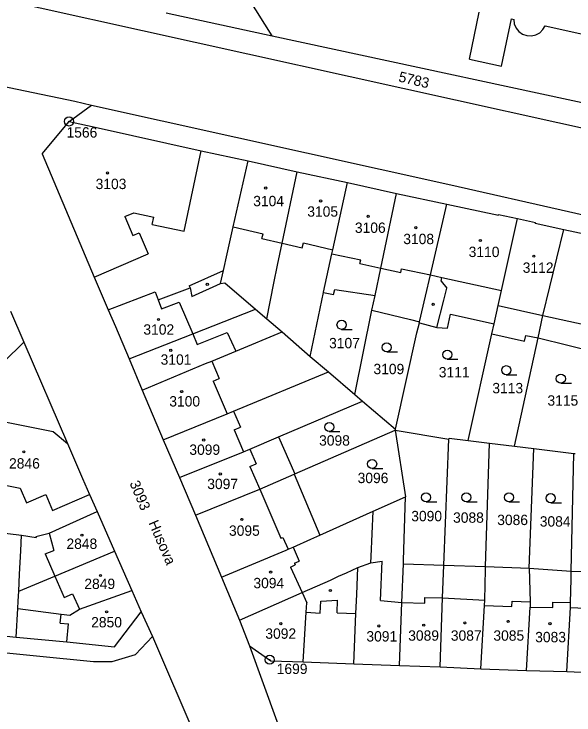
# Model space of a CAD drawing. Extents: x -735092 to -733385, y -1122435 to -1118992.
# Drawn here: x -734755 to -734663.1, y -1120137.2 to -1120022.1 of the extents above; entities that cross this region are included whole.
import ezdxf

# ---------------------------------------------------------------- set-up
doc = ezdxf.new("R2010")
doc.units = 0
for name, color, linetype in [('Vrstva 1', 7, 'Continuous'), ('Vrstva 15', 7, 'Continuous'), ('Vrstva 17', 7, 'Continuous'), ('Vrstva 18', 7, 'Continuous'), ('Vrstva 19', 7, 'Continuous'), ('Vrstva 25', 7, 'Continuous'), ('Vrstva 4', 7, 'Continuous')]:
    doc.layers.add(name, color=color, linetype=linetype)

msp = doc.modelspace()

# ---------------------------------------------------------------- linework, layer by layer
at = {"layer": 'Vrstva 1'}
for points in [[(-734712.66, -1120025.63), (-734719.23, -1120015.12)], [(-734759.44, -1120019.08), (-734622.96, -1120049.35)], [(-734730.04, -1120021.87), (-734712.66, -1120025.63)], [(-734680.22, -1120029.49), (-734678.62, -1120021.76)], [(-734674.99, -1120030.64), (-734673.34, -1120022.87)], [(-734673.34, -1120022.87), (-734672.95, -1120022.95)], [(-734672.95, -1120022.95), (-734672.86, -1120023.68)], [(-734672.86, -1120023.68), (-734672.57, -1120024.36)], [(-734672.57, -1120024.36), (-734672.1, -1120024.94)], [(-734668.17, -1120024.62), (-734667.8, -1120023.98)], [(-734667.8, -1120023.98), (-734657.17, -1120026.38)], [(-734712.66, -1120025.63), (-734649.52, -1120039.21)], [(-734672.1, -1120024.94), (-734671.5, -1120025.36)], [(-734671.5, -1120025.36), (-734670.8, -1120025.6)], [(-734670.8, -1120025.6), (-734670.06, -1120025.64)], [(-734670.06, -1120025.64), (-734669.34, -1120025.48)], [(-734669.34, -1120025.48), (-734668.69, -1120025.13)], [(-734668.69, -1120025.13), (-734668.17, -1120024.62)], [(-734680.22, -1120029.49), (-734674.99, -1120030.64)], [(-734773.55, -1120030.48), (-734745.06, -1120036.39)], [(-734746.01, -1120039.7), (-734742.29, -1120037.01)], [(-734745.06, -1120036.39), (-734742.29, -1120037.01)], [(-734742.29, -1120037.01), (-734683.27, -1120050.12)], [(-734750.43, -1120045), (-734746.01, -1120039.7)], [(-734746.01, -1120039.7), (-734741.21, -1120040.76)], [(-734741.21, -1120040.76), (-734724.28, -1120044.52)], [(-734750.43, -1120045), (-734741.89, -1120065.28)], [(-734724.28, -1120044.52), (-734716.58, -1120046.19)], [(-734719.02, -1120057.03), (-734716.58, -1120046.19)], [(-734716.58, -1120046.19), (-734708.51, -1120047.95)], [(-734711.01, -1120059.7), (-734708.51, -1120047.95)], [(-734708.51, -1120047.95), (-734700.29, -1120049.73)], [(-734702.69, -1120060.78), (-734700.29, -1120049.73)], [(-734700.29, -1120049.73), (-734692.22, -1120051.53)], [(-734683.27, -1120050.12), (-734625.28, -1120063.27)], [(-734694.8, -1120063.78), (-734692.22, -1120051.53)], [(-734692.22, -1120051.53), (-734683.93, -1120053.29)], [(-734686.63, -1120064.91), (-734683.93, -1120053.29)], [(-734683.93, -1120053.29), (-734675.47, -1120055.11)], [(-734675.47, -1120055.11), (-734675.44, -1120054.97)], [(-734675.44, -1120054.97), (-734672.36, -1120055.63)], [(-734674.98, -1120067.47), (-734672.36, -1120055.63)], [(-734672.36, -1120055.63), (-734669.4, -1120056.27)], [(-734669.43, -1120056.41), (-734669.4, -1120056.27)], [(-734669.43, -1120056.41), (-734664.74, -1120057.42)], [(-734720.02, -1120061.44), (-734719.02, -1120057.03)], [(-734668.15, -1120071.54), (-734664.74, -1120057.42)], [(-734664.74, -1120057.42), (-734658.29, -1120058.81)], [(-734711.75, -1120063.31), (-734711.01, -1120059.7)], [(-734704.2, -1120067.71), (-734702.83, -1120061.43)], [(-734702.83, -1120061.43), (-734702.69, -1120060.78)], [(-734720.64, -1120064.2), (-734720.02, -1120061.44)], [(-734712.35, -1120066.27), (-734711.75, -1120063.31)], [(-734721.12, -1120066.31), (-734720.64, -1120064.2)], [(-734695.74, -1120068.26), (-734694.8, -1120063.78)], [(-734741.89, -1120065.28), (-734739.58, -1120070.62)], [(-734687.44, -1120068.41), (-734686.63, -1120064.91)], [(-734731.38, -1120068.98), (-734726.12, -1120067.04)], [(-734726.12, -1120067.04), (-734725.84, -1120068.43)], [(-734725.84, -1120068.43), (-734721.12, -1120066.31)], [(-734721.12, -1120066.31), (-734720.44, -1120066.19)], [(-734720.44, -1120066.19), (-734715.39, -1120070.51)], [(-734713.54, -1120072.09), (-734712.35, -1120066.27)], [(-734739.58, -1120070.62), (-734731.88, -1120067.67)], [(-734731.88, -1120067.67), (-734731.38, -1120068.98)], [(-734706.4, -1120078.29), (-734704.22, -1120067.79)], [(-734704.22, -1120067.79), (-734704.2, -1120067.71)], [(-734704.22, -1120067.79), (-734702.54, -1120068.14)], [(-734702.54, -1120068.14), (-734702.37, -1120067.32)], [(-734702.37, -1120067.32), (-734695.74, -1120068.26)], [(-734696.24, -1120070.7), (-734695.74, -1120068.26)], [(-734675.52, -1120069.92), (-734674.98, -1120067.47)], [(-734688.41, -1120072.59), (-734687.44, -1120068.41)], [(-734739.58, -1120070.62), (-734738.38, -1120073.38)], [(-734725.68, -1120074.58), (-734715.39, -1120070.51)], [(-734715.39, -1120070.51), (-734713.54, -1120072.09)], [(-734676.18, -1120072.92), (-734675.52, -1120069.92)], [(-734755.61, -1120070.88), (-734753.42, -1120075.94)], [(-734699.07, -1120084.53), (-734696.24, -1120070.7)], [(-734696.24, -1120070.7), (-734689.9, -1120072.25)], [(-734683.86, -1120073.64), (-734683.35, -1120071.33)], [(-734683.35, -1120071.33), (-734676.18, -1120072.92)], [(-734668.96, -1120075.25), (-734668.15, -1120071.54)], [(-734713.54, -1120072.09), (-734710.98, -1120074.27)], [(-734689.9, -1120072.25), (-734688.41, -1120072.59)], [(-734688.87, -1120074.42), (-734688.46, -1120072.79)], [(-734688.46, -1120072.79), (-734688.41, -1120072.59)], [(-734688.46, -1120072.79), (-734685.58, -1120073.52)], [(-734676.55, -1120074.57), (-734676.18, -1120072.92)], [(-734738.38, -1120073.38), (-734736.13, -1120078.7)], [(-734685.58, -1120073.52), (-734683.86, -1120073.64)], [(-734736.13, -1120078.7), (-734725.68, -1120074.58)], [(-734718.6, -1120077.41), (-734710.98, -1120074.27)], [(-734710.98, -1120074.27), (-734706.4, -1120078.29)], [(-734692.37, -1120090.23), (-734688.87, -1120074.42)], [(-734680.42, -1120092.08), (-734676.55, -1120074.57)], [(-734676.55, -1120074.57), (-734671.19, -1120075.76)], [(-734671.19, -1120075.76), (-734670.99, -1120074.84)], [(-734670.99, -1120074.84), (-734668.96, -1120075.25)], [(-734756.74, -1120079.17), (-734753.42, -1120075.94)], [(-734753.42, -1120075.94), (-734746.27, -1120092.6)], [(-734672.81, -1120093.01), (-734668.96, -1120075.25)], [(-734668.96, -1120075.25), (-734659.21, -1120077.63)], [(-734722.56, -1120079.04), (-734718.6, -1120077.41)], [(-734706.4, -1120078.29), (-734703.41, -1120080.84)], [(-734736.13, -1120078.7), (-734734, -1120083.8)], [(-734734, -1120083.8), (-734723.58, -1120079.46)], [(-734723.58, -1120079.46), (-734722.56, -1120079.04)], [(-734718.98, -1120087.3), (-734703.41, -1120080.84)], [(-734703.41, -1120080.84), (-734699.07, -1120084.53)], [(-734734, -1120083.8), (-734730.53, -1120091.97)], [(-734699.07, -1120084.53), (-734697.79, -1120085.62)], [(-734711.61, -1120091.5), (-734697.79, -1120085.62)], [(-734697.79, -1120085.62), (-734692.37, -1120090.23)], [(-734730.53, -1120091.97), (-734720.01, -1120087.73)], [(-734720.01, -1120087.73), (-734718.98, -1120087.3)], [(-734759.88, -1120088.36), (-734748.62, -1120090.64)], [(-734748.62, -1120090.64), (-734746.27, -1120092.6)], [(-734708.91, -1120097.56), (-734692.41, -1120090.4)], [(-734692.41, -1120090.4), (-734692.37, -1120090.23)], [(-734692.41, -1120090.4), (-734690.71, -1120101.34)], [(-734692.41, -1120090.4), (-734683.6, -1120091.87)], [(-734730.53, -1120091.97), (-734727.88, -1120098.19)], [(-734716.31, -1120093.5), (-734711.61, -1120091.5)], [(-734711.61, -1120091.5), (-734708.91, -1120097.56)], [(-734684.42, -1120112.56), (-734683.6, -1120091.87)], [(-734683.6, -1120091.87), (-734683.59, -1120091.7)], [(-734683.59, -1120091.7), (-734680.42, -1120092.08)], [(-734680.42, -1120092.08), (-734676.96, -1120092.51)], [(-734677.59, -1120112.79), (-734676.96, -1120092.51)], [(-734676.96, -1120092.51), (-734672.81, -1120093.01)], [(-734746.27, -1120092.6), (-734743.81, -1120098.34)], [(-734717.33, -1120093.93), (-734716.31, -1120093.5)], [(-734672.81, -1120093.01), (-734669.67, -1120093.4)], [(-734670.4, -1120113.05), (-734669.67, -1120093.4)], [(-734669.67, -1120093.4), (-734663.11, -1120094.23)], [(-734727.88, -1120098.19), (-734717.33, -1120093.93)], [(-734663.52, -1120113.54), (-734663.11, -1120094.23)], [(-734663.11, -1120094.23), (-734662.86, -1120094.24)], [(-734727.88, -1120098.19), (-734725.22, -1120104.37)], [(-734714.69, -1120100.06), (-734709.02, -1120097.6)], [(-734709.02, -1120097.6), (-734708.91, -1120097.56)], [(-734709.02, -1120097.6), (-734704.79, -1120107.63)], [(-734743.81, -1120098.34), (-734742.65, -1120100.94)], [(-734725.22, -1120104.37), (-734714.69, -1120100.06)], [(-734742.65, -1120100.94), (-734741.41, -1120103.73)], [(-734696.03, -1120103.72), (-734690.71, -1120101.34)], [(-734691.04, -1120111.73), (-734690.71, -1120101.34)], [(-734749.29, -1120107.32), (-734741.41, -1120103.73)], [(-734741.41, -1120103.73), (-734738.55, -1120110.28)], [(-734704.79, -1120107.63), (-734696.03, -1120103.72)], [(-734696.4, -1120111.12), (-734696.03, -1120103.72)], [(-734978.31, -1120104.89), (-734741.96, -1120128.37)], [(-734725.22, -1120104.37), (-734720.97, -1120114.53)], [(-734762.86, -1120106.55), (-734753.79, -1120107.64)], [(-734751.46, -1120107.88), (-734749.29, -1120107.32)], [(-734753.92, -1120110.19), (-734753.79, -1120107.64)], [(-734753.79, -1120107.64), (-734751.4, -1120108.03)], [(-734751.46, -1120107.88), (-734751.4, -1120108.03)], [(-734709.2, -1120109.6), (-734706.3, -1120108.3)], [(-734706.3, -1120108.3), (-734704.79, -1120107.63)], [(-734710.03, -1120109.96), (-734709.2, -1120109.6)], [(-734754.12, -1120114.04), (-734753.92, -1120110.19)], [(-734748.32, -1120114.37), (-734738.55, -1120110.28)], [(-734738.55, -1120110.28), (-734735.7, -1120116.71)], [(-734720.97, -1120114.53), (-734710.35, -1120110.11)], [(-734710.35, -1120110.11), (-734710.03, -1120109.96)], [(-734696.45, -1120112.2), (-734696.4, -1120111.12)], [(-734691.06, -1120112.35), (-734691.04, -1120111.73)], [(-734700.44, -1120113.83), (-734698.55, -1120112.94)], [(-734698.74, -1120117.36), (-734698.55, -1120112.94)], [(-734698.55, -1120112.94), (-734696.45, -1120112.2)], [(-734691.32, -1120118.72), (-734691.06, -1120112.35)], [(-734691.06, -1120112.35), (-734684.42, -1120112.56)], [(-734684.64, -1120117.95), (-734684.42, -1120112.56)], [(-734684.42, -1120112.56), (-734677.59, -1120112.79)], [(-734677.6, -1120113.26), (-734677.59, -1120112.79)], [(-734677.59, -1120112.79), (-734670.4, -1120113.05)], [(-734670.4, -1120113.05), (-734663.52, -1120113.54)], [(-734670.4, -1120113.05), (-734670.28, -1120118.59)], [(-734754.25, -1120116.86), (-734754.12, -1120114.04)], [(-734754.25, -1120116.86), (-734748.32, -1120114.37)], [(-734703.08, -1120115.02), (-734701.75, -1120114.37)], [(-734701.75, -1120114.37), (-734700.44, -1120113.83)], [(-734677.72, -1120118.31), (-734677.6, -1120113.26)], [(-734663.55, -1120114.85), (-734663.52, -1120113.54)], [(-734663.52, -1120113.54), (-734658.19, -1120113.59)], [(-734720.97, -1120114.53), (-734717.99, -1120121.62)], [(-734707.73, -1120117.04), (-734703.08, -1120115.02)], [(-734663.62, -1120118.67), (-734663.55, -1120114.85)], [(-734754.35, -1120118.5), (-734754.25, -1120116.86)], [(-734744.27, -1120119.8), (-734735.7, -1120116.71)], [(-734735.7, -1120116.71), (-734734.16, -1120120.2)], [(-734717.99, -1120121.62), (-734707.73, -1120117.04)], [(-734698.88, -1120120.5), (-734698.74, -1120117.36)], [(-734754.43, -1120119.69), (-734754.35, -1120118.5)], [(-734691.73, -1120129.02), (-734691.32, -1120118.72)], [(-734685.05, -1120129.27), (-734684.64, -1120117.95)], [(-734677.74, -1120119.17), (-734677.72, -1120118.31)], [(-734670.28, -1120118.59), (-734670.26, -1120119.45)], [(-734663.63, -1120119.54), (-734663.62, -1120118.67)], [(-734754.69, -1120124.4), (-734754.43, -1120119.69)], [(-734754.43, -1120119.69), (-734747.32, -1120120.59)], [(-734745.89, -1120120.77), (-734744.27, -1120119.8)], [(-734678.37, -1120129.56), (-734677.74, -1120119.17)], [(-734670.88, -1120129.86), (-734670.26, -1120119.45)], [(-734664.23, -1120130.05), (-734663.63, -1120119.54)], [(-734747.32, -1120120.59), (-734745.89, -1120120.77)], [(-734738.56, -1120125.97), (-734734.16, -1120120.2)], [(-734734.16, -1120120.2), (-734732.31, -1120124.29)], [(-734699.23, -1120128.75), (-734698.88, -1120120.5)], [(-734717.99, -1120121.62), (-734716.35, -1120125.79)], [(-734759.45, -1120123.9), (-734754.69, -1120124.4)], [(-734754.69, -1120124.4), (-734746.39, -1120125.14)], [(-734735.07, -1120127.22), (-734732.31, -1120124.29)], [(-734732.31, -1120124.29), (-734725.18, -1120140.86)], [(-734746.39, -1120125.14), (-734738.56, -1120125.97)], [(-734716.35, -1120125.79), (-734713.42, -1120127.87)], [(-734716.35, -1120125.79), (-734709.6, -1120144.34)], [(-734738.9, -1120128.4), (-734735.07, -1120127.22)], [(-734713.42, -1120127.87), (-734712.88, -1120128.26)], [(-734741.96, -1120128.37), (-734738.9, -1120128.4)], [(-734712.88, -1120128.26), (-734707.54, -1120128.46)], [(-734707.54, -1120128.46), (-734699.23, -1120128.75)], [(-734699.23, -1120128.75), (-734691.73, -1120129.02)], [(-734691.73, -1120129.02), (-734685.05, -1120129.27)], [(-734685.05, -1120129.27), (-734678.37, -1120129.56)], [(-734678.37, -1120129.56), (-734670.88, -1120129.86)], [(-734670.88, -1120129.86), (-734664.23, -1120130.05)], [(-734664.23, -1120130.05), (-734653.23, -1120130.5)]]:
    msp.add_lwpolyline(points, dxfattribs=at)
at = {"layer": 'Vrstva 25'}
for points in [[(-734701.24, -1120073.84), (-734699.49, -1120073.84)], [(-734693.82, -1120077.55), (-734692.07, -1120077.55)], [(-734683.88, -1120078.74), (-734682.13, -1120078.74)], [(-734674.18, -1120081.3), (-734672.43, -1120081.3)], [(-734665.22, -1120082.69), (-734663.47, -1120082.69)], [(-734703.26, -1120090.64), (-734701.51, -1120090.64)], [(-734696.22, -1120096.7), (-734694.47, -1120096.7)], [(-734687.36, -1120102.18), (-734685.61, -1120102.18)], [(-734680.74, -1120102.18), (-734678.99, -1120102.18)], [(-734673.75, -1120102.18), (-734672, -1120102.18)], [(-734666.88, -1120102.31), (-734665.13, -1120102.31)]]:
    msp.add_lwpolyline(points, dxfattribs=at)
for centre, radius in [((-734746.01, -1120039.7), 0.75), ((-734746.01, -1120039.7), 0.032), ((-734739.7, -1120048.16), 0.175), ((-734713.7, -1120050.64), 0.175), ((-734704.68, -1120052.76), 0.175), ((-734696.86, -1120055.28), 0.175), ((-734689.04, -1120057.14), 0.175), ((-734678.44, -1120059.26), 0.175), ((-734669.65, -1120061.81), 0.175), ((-734723.29, -1120066.44), 0.175), ((-734686.2, -1120069.74), 0.175), ((-734731.32, -1120072.23), 0.175), ((-734701.24, -1120073.09), 0.75), ((-734693.82, -1120076.8), 0.75), ((-734729.3, -1120077.29), 0.175), ((-734683.88, -1120077.99), 0.75), ((-734674.18, -1120080.55), 0.75), ((-734665.22, -1120081.94), 0.75), ((-734727.5, -1120084.06), 0.175), ((-734703.26, -1120089.89), 0.75), ((-734723.89, -1120092.02), 0.175), ((-734753.42, -1120093.95), 0.175), ((-734696.22, -1120095.95), 0.75), ((-734721.16, -1120097.59), 0.174), ((-734687.36, -1120101.43), 0.75), ((-734680.74, -1120101.43), 0.75), ((-734673.75, -1120101.43), 0.75), ((-734666.88, -1120101.56), 0.75), ((-734717.62, -1120105.05), 0.175), ((-734743.89, -1120107.65), 0.175), ((-734740.85, -1120114.25), 0.175), ((-734712.89, -1120113.7), 0.175), ((-734703.08, -1120116.73), 0.175), ((-734739.83, -1120120.24), 0.175), ((-734711.22, -1120122.17), 0.175), ((-734695.11, -1120122.55), 0.175), ((-734687.74, -1120122.42), 0.175), ((-734680.99, -1120122.05), 0.175), ((-734673.87, -1120121.8), 0.175), ((-734667, -1120122.17), 0.175), ((-734713.05, -1120128.09), 0.75), ((-734713.05, -1120128.09), 0.032)]:
    msp.add_circle(centre, radius, dxfattribs=at)
at = {"layer": 'Vrstva 4'}
for points in [[(-734727.08, -1120057.7), (-734724.28, -1120044.52)], [(-734736.83, -1120055.33), (-734735.35, -1120054.73)], [(-734736.83, -1120055.33), (-734735.52, -1120058.43)], [(-734735.35, -1120054.73), (-734732.09, -1120055.4)], [(-734732.34, -1120056.63), (-734732.09, -1120055.4)], [(-734732.34, -1120056.63), (-734727.08, -1120057.7)], [(-734719.02, -1120057.03), (-734714.13, -1120058.15)], [(-734735.52, -1120058.43), (-734734.49, -1120057.99)], [(-734734.49, -1120057.99), (-734733.02, -1120061.42)], [(-734714.34, -1120058.94), (-734714.13, -1120058.15)], [(-734714.34, -1120058.94), (-734711.01, -1120059.7)], [(-734711.01, -1120059.7), (-734707.69, -1120060.47)], [(-734707.69, -1120060.47), (-734707.5, -1120059.66)], [(-734707.5, -1120059.66), (-734702.69, -1120060.78)], [(-734741.89, -1120065.28), (-734733.02, -1120061.42)], [(-734702.83, -1120061.43), (-734698.1, -1120062.45)], [(-734698.22, -1120063.01), (-734698.1, -1120062.45)], [(-734698.22, -1120063.01), (-734694.8, -1120063.78)], [(-734726.28, -1120066.68), (-734720.64, -1120064.2)], [(-734694.8, -1120063.78), (-734691.5, -1120064.49)], [(-734691.5, -1120064.49), (-734691.37, -1120063.89)], [(-734691.37, -1120063.89), (-734686.63, -1120064.91)], [(-734686.63, -1120064.91), (-734684.76, -1120065.32)], [(-734684.9, -1120065.93), (-734684.76, -1120065.32)], [(-734684.9, -1120065.93), (-734683.94, -1120067.07)], [(-734684.76, -1120065.32), (-734674.98, -1120067.47)], [(-734726.28, -1120066.68), (-734726.12, -1120067.04)], [(-734684.45, -1120069.06), (-734683.94, -1120067.07)], [(-734731.38, -1120068.98), (-734730.8, -1120070.47)], [(-734730.8, -1120070.47), (-734727.93, -1120069.37)], [(-734727.93, -1120069.37), (-734725.68, -1120074.58)], [(-734685.58, -1120073.52), (-734684.45, -1120069.06)], [(-734675.52, -1120069.92), (-734668.15, -1120071.54)], [(-734668.15, -1120071.54), (-734658.35, -1120073.69)], [(-734725.68, -1120074.58), (-734724.94, -1120076.31)], [(-734724.94, -1120076.31), (-734720.01, -1120074.35)], [(-734720.01, -1120074.35), (-734718.6, -1120077.41)], [(-734722.56, -1120079.04), (-734721.33, -1120081.9)], [(-734722.34, -1120082.33), (-734721.33, -1120081.9)], [(-734722.34, -1120082.33), (-734720.01, -1120087.73)], [(-734718.98, -1120087.3), (-734717.86, -1120089.88)], [(-734718.89, -1120090.33), (-734717.86, -1120089.88)], [(-734718.89, -1120090.33), (-734717.33, -1120093.93)], [(-734716.31, -1120093.5), (-734715.26, -1120095.92)], [(-734716.28, -1120096.36), (-734715.26, -1120095.92)], [(-734716.28, -1120096.36), (-734714.69, -1120100.06)], [(-734761.53, -1120098.46), (-734754.05, -1120099.92)], [(-734754.05, -1120099.92), (-734753.01, -1120102.32)], [(-734714.69, -1120100.06), (-734711.19, -1120108.15)], [(-734753.01, -1120102.32), (-734749.84, -1120100.95)], [(-734749.84, -1120100.95), (-734748.71, -1120103.56)], [(-734748.71, -1120103.56), (-734742.65, -1120100.94)], [(-734749.29, -1120107.32), (-734748.53, -1120110.13)], [(-734711.19, -1120108.15), (-734710.87, -1120108.02)], [(-734710.87, -1120108.02), (-734710.03, -1120109.96)], [(-734709.2, -1120109.6), (-734708.18, -1120111.9)], [(-734749.9, -1120110.72), (-734748.53, -1120110.13)], [(-734749.9, -1120110.72), (-734748.32, -1120114.37)], [(-734708.97, -1120112.26), (-734708.18, -1120111.9)], [(-734696.45, -1120112.2), (-734694.58, -1120111.93)], [(-734694.83, -1120118.38), (-734694.58, -1120111.93)], [(-734709.63, -1120112.89), (-734708.85, -1120112.53)], [(-734709.63, -1120112.89), (-734707.73, -1120117.04)], [(-734708.97, -1120112.26), (-734708.85, -1120112.53)], [(-734748.32, -1120114.37), (-734746.8, -1120117.88)], [(-734746.8, -1120117.88), (-734745.41, -1120117.28)], [(-734745.41, -1120117.28), (-734744.27, -1120119.8)], [(-734707.73, -1120117.04), (-734706.95, -1120118.75)], [(-734707.04, -1120120.3), (-734706.95, -1120118.75)], [(-734704.76, -1120120.44), (-734704.64, -1120118.47)], [(-734704.64, -1120118.47), (-734701.88, -1120118.32)], [(-734701.95, -1120120.37), (-734701.88, -1120118.32)], [(-734694.83, -1120118.38), (-734691.32, -1120118.72)], [(-734691.32, -1120118.72), (-734687.56, -1120118.78)], [(-734687.56, -1120118.78), (-734687.55, -1120117.9)], [(-734687.55, -1120117.9), (-734684.64, -1120117.95)], [(-734684.64, -1120117.95), (-734677.72, -1120118.31)], [(-734673.27, -1120119.36), (-734673.23, -1120118.47)], [(-734673.23, -1120118.47), (-734670.28, -1120118.59)], [(-734666.55, -1120119.51), (-734666.53, -1120118.62)], [(-734666.53, -1120118.62), (-734663.62, -1120118.67)], [(-734677.74, -1120119.17), (-734673.27, -1120119.36)], [(-734670.26, -1120119.45), (-734666.55, -1120119.51)], [(-734663.63, -1120119.54), (-734660.01, -1120119.69)], [(-734747.48, -1120122.09), (-734747.32, -1120120.59)], [(-734707.54, -1120128.46), (-734707.04, -1120120.3)], [(-734707.04, -1120120.3), (-734704.76, -1120120.44)], [(-734701.95, -1120120.37), (-734698.88, -1120120.5)], [(-734747.48, -1120122.09), (-734746.1, -1120122.21)], [(-734746.39, -1120125.14), (-734746.1, -1120122.21)]]:
    msp.add_lwpolyline(points, dxfattribs=at)

# ---------------------------------------------------------------- texts
at = {"layer": 'Vrstva 15'}
msp.add_text('Husova', height=1.7, rotation=293.20233, dxfattribs=at).set_placement((-734732.988, -1120105.615))
at = {"layer": 'Vrstva 17'}
for s, p in [('1566', (-734746.42, -1120042.35)), ('1699', (-734711.89, -1120130.44))]:
    msp.add_text(s, height=1.7, dxfattribs=at).set_placement(p)
at = {"layer": 'Vrstva 18'}
for s, rotation, p in [('5783', 346.80276, (-734691.99, -1120033.121)), ('3093', 292.80233, (-734736.099, -1120099.086))]:
    msp.add_text(s, height=1.7, rotation=rotation, dxfattribs=at).set_placement(p)
for s, p in [('3107', (-734703.29, -1120076.95)), ('3109', (-734696, -1120081.2)), ('3111', (-734685.27, -1120081.73)), ('3113', (-734676.47, -1120084.34)), ('3115', (-734667.42, -1120086.37)), ('3098', (-734704.93, -1120092.93)), ('3096', (-734698.6, -1120099.09)), ('3090', (-734689.79, -1120105.35)), ('3088', (-734682.92, -1120105.6)), ('3086', (-734675.67, -1120105.98)), ('3084', (-734668.68, -1120106.23))]:
    msp.add_text(s, height=1.7, dxfattribs=at).set_placement(p)
at = {"layer": 'Vrstva 19'}
for s, p in [('3103', (-734741.64, -1120050.81)), ('3104', (-734715.75, -1120053.62)), ('3105', (-734706.87, -1120055.34)), ('3106', (-734699.05, -1120058)), ('3108', (-734691.1, -1120059.85)), ('3110', (-734680.36, -1120061.97)), ('3112', (-734671.48, -1120064.56)), ('3102', (-734733.79, -1120074.71)), ('3101', (-734730.96, -1120079.65)), ('3100', (-734729.54, -1120086.51)), ('3099', (-734726.24, -1120094.45)), ('2846', (-734755.86, -1120096.7)), ('3097', (-734723.3, -1120100.07)), ('3095', (-734719.73, -1120107.74)), ('2848', (-734746.43, -1120109.89)), ('2849', (-734743.49, -1120116.48)), ('3094', (-734715.72, -1120116.35)), ('2850', (-734742.37, -1120122.78)), ('3092', (-734713.76, -1120124.65)), ('3091', (-734697.16, -1120125.1)), ('3089', (-734690.29, -1120124.97)), ('3087', (-734683.29, -1120124.97)), ('3085', (-734676.3, -1120124.97)), ('3083', (-734669.43, -1120125.22))]:
    msp.add_text(s, height=1.7, dxfattribs=at).set_placement(p)

doc.saveas('drawing.dxf')
